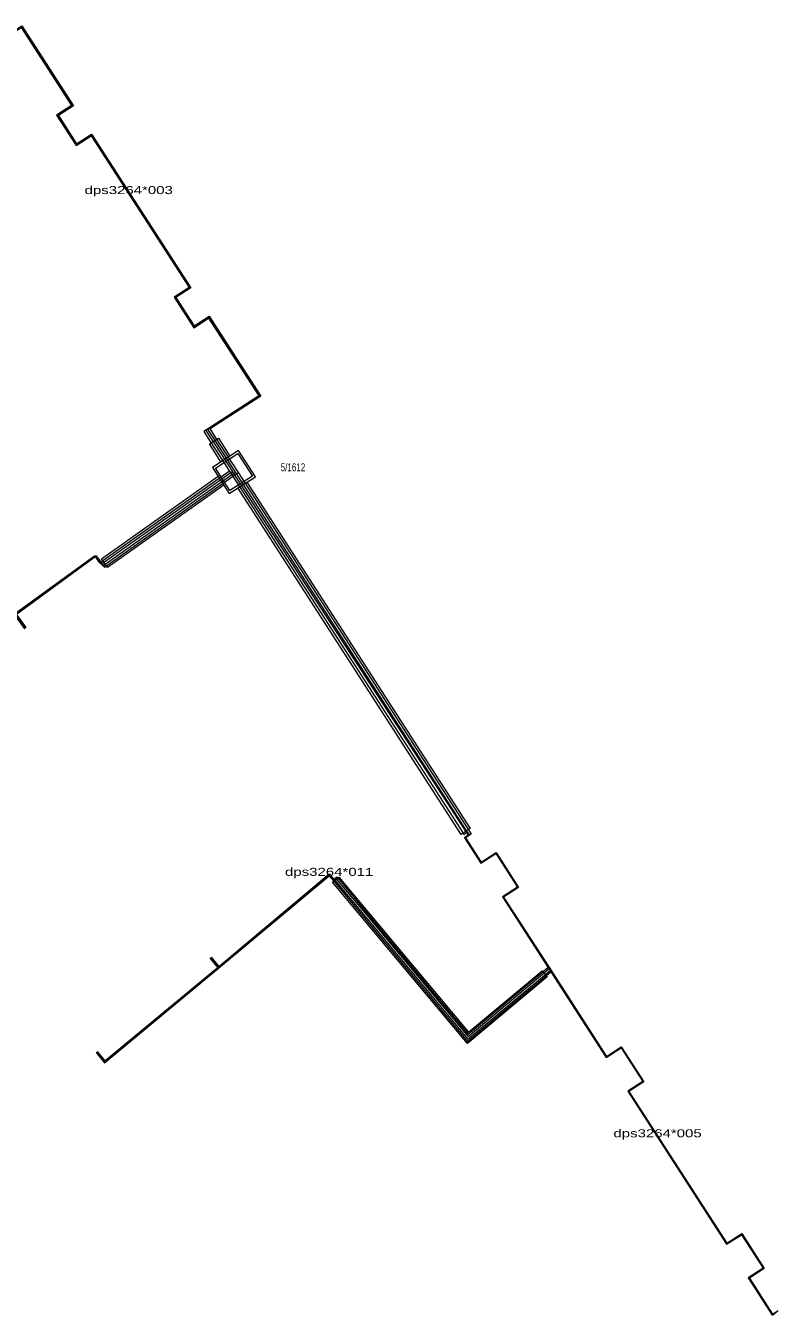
# Model space of a CAD drawing. Extents: x -473467 to -473049, y -1106745 to -1106181.
# Drawn here: x -473234.1 to -473149.4, y -1106405.6 to -1106261.1 of the extents above; entities that cross this region are included whole.
import ezdxf
from ezdxf.enums import TextEntityAlignment as Align

# ---------------------------------------------------------------- set-up
doc = ezdxf.new("R2010")
doc.units = 0
doc.header["$LTSCALE"] = 0.36
for name, color, linetype, lineweight in [('11', 7, 'Continuous', 13), ('14', 7, 'Continuous', 13), ('17', 7, 'Continuous', 13)]:
    doc.layers.add(name, color=color, linetype=linetype, lineweight=lineweight)
doc.layers.add('16', color=7, linetype='Continuous')
doc.layers.add('19', color=7, linetype='Continuous')

msp = doc.modelspace()

# ---------------------------------------------------------------- linework, layer by layer
at = {"layer": '11'}
for p, q in [((-473213.287, -1106307.887), (-473211.131, -1106311.23)), ((-473213.088, -1106307.753), (-473210.807, -1106311.29)), ((-473212.886, -1106307.623), (-473210.487, -1106311.344)), ((-473212.691, -1106307.484), (-473210.166, -1106311.398)), ((-473225.749, -1106321.547), (-473211.136, -1106311.222)), ((-473225.567, -1106321.71), (-473210.812, -1106311.283)), ((-473184.47, -1106351.851), (-473210.807, -1106311.29)), ((-473225.389, -1106321.873), (-473210.489, -1106311.341)), ((-473225.204, -1106322.031), (-473210.161, -1106311.406)), ((-473199.906, -1106356.614), (-473199.394, -1106357.227)), ((-473199.899, -1106356.544), (-473199.387, -1106357.156)), ((-473199.444, -1106357.323), (-473195.783, -1106361.702))]:
    msp.add_line(p, q, dxfattribs=at)
for points in [[(-473238.707, -1106262.643), (-473238.074, -1106263.624), (-473234.545, -1106261.347), (-473228.897, -1106270.104), (-473230.578, -1106271.188), (-473228.367, -1106274.617), (-473226.686, -1106273.533), (-473215.683, -1106290.594), (-473217.364, -1106291.678), (-473215.152, -1106295.107), (-473213.472, -1106294.023), (-473207.824, -1106302.78), (-473213.374, -1106306.359), (-473213.458, -1106306.413), (-473214.009, -1106306.769), (-473213.287, -1106307.887)], [(-473238.667, -1106262.612), (-473238.06, -1106263.555), (-473234.53, -1106261.278), (-473228.828, -1106270.119), (-473230.509, -1106271.203), (-473228.352, -1106274.548), (-473226.671, -1106273.464), (-473215.614, -1106290.609), (-473217.295, -1106291.693), (-473215.137, -1106295.038), (-473213.457, -1106293.954), (-473207.755, -1106302.795), (-473213.347, -1106306.401), (-473213.389, -1106306.428), (-473213.78, -1106306.68), (-473213.088, -1106307.753)], [(-473238.628, -1106262.581), (-473238.045, -1106263.486), (-473234.515, -1106261.209), (-473228.759, -1106270.134), (-473230.44, -1106271.218), (-473228.337, -1106274.479), (-473226.656, -1106273.395), (-473215.545, -1106290.624), (-473217.225, -1106291.708), (-473215.123, -1106294.969), (-473213.442, -1106293.885), (-473207.686, -1106302.81), (-473213.551, -1106306.592), (-473212.886, -1106307.623)], [(-473238.589, -1106262.55), (-473238.03, -1106263.416), (-473234.5, -1106261.14), (-473228.69, -1106270.149), (-473230.371, -1106271.233), (-473228.322, -1106274.41), (-473226.641, -1106273.326), (-473215.476, -1106290.639), (-473217.156, -1106291.723), (-473215.108, -1106294.9), (-473213.427, -1106293.816), (-473207.617, -1106302.825), (-473213.293, -1106306.485), (-473213.322, -1106306.504), (-473212.691, -1106307.484)], [(-473211.131, -1106311.23), (-473184.855, -1106351.973), (-473184.779, -1106352.091), (-473184.477, -1106351.896)], [(-473210.487, -1106311.344), (-473184.452, -1106351.713), (-473184.148, -1106352.184)], [(-473210.166, -1106311.398), (-473184.25, -1106351.583), (-473183.93, -1106352.079)], [(-473262.006, -1106346.747), (-473261.761, -1106346.568), (-473260.583, -1106348.184), (-473261.761, -1106346.568), (-473247.401, -1106336.104), (-473246.223, -1106337.72), (-473247.401, -1106336.104), (-473235.214, -1106327.223), (-473234.036, -1106328.84), (-473235.214, -1106327.223), (-473226.331, -1106320.75), (-473225.749, -1106321.547)], [(-473261.974, -1106346.785), (-473261.772, -1106346.637), (-473260.627, -1106348.212), (-473261.772, -1106346.637), (-473247.412, -1106336.173), (-473246.268, -1106337.757), (-473247.412, -1106336.173), (-473235.225, -1106327.293), (-473234.075, -1106328.867), (-473235.225, -1106327.293), (-473226.26, -1106320.76), (-473225.567, -1106321.71)], [(-473261.943, -1106346.824), (-473261.783, -1106346.707), (-473260.665, -1106348.257), (-473261.783, -1106346.707), (-473247.423, -1106336.243), (-473246.301, -1106337.796), (-473247.423, -1106336.243), (-473235.236, -1106327.363), (-473234.12, -1106328.911), (-473235.236, -1106327.363), (-473226.192, -1106320.772), (-473225.389, -1106321.873)], [(-473261.913, -1106346.865), (-473261.794, -1106346.777), (-473260.704, -1106348.284), (-473261.794, -1106346.777), (-473247.434, -1106336.313), (-473246.357, -1106337.834), (-473247.434, -1106336.313), (-473235.247, -1106327.433), (-473234.142, -1106328.961), (-473235.247, -1106327.433), (-473226.116, -1106320.779), (-473225.204, -1106322.031)], [(-473184.477, -1106351.896), (-473184.282, -1106352.198), (-473184.702, -1106352.469), (-473182.854, -1106355.335), (-473181.173, -1106354.251), (-473178.734, -1106358.033), (-473180.415, -1106359.117), (-473174.972, -1106367.556)], [(-473184.47, -1106351.851), (-473184.24, -1106352.207), (-473184.661, -1106352.478), (-473182.845, -1106355.294), (-473181.164, -1106354.21), (-473178.693, -1106358.042), (-473180.373, -1106359.126), (-473175.045, -1106367.388)], [(-473184.148, -1106352.184), (-473184.199, -1106352.216), (-473184.619, -1106352.487), (-473182.836, -1106355.252), (-473181.155, -1106354.168), (-473178.651, -1106358.051), (-473180.332, -1106359.135), (-473175.141, -1106367.183)], [(-473183.93, -1106352.079), (-473184.157, -1106352.225), (-473184.578, -1106352.496), (-473182.827, -1106355.211), (-473181.146, -1106354.127), (-473178.61, -1106358.06), (-473180.29, -1106359.144), (-473175.225, -1106366.998)], [(-473226.14, -1106376.613), (-473225.183, -1106377.768), (-473212.361, -1106367.157), (-473213.317, -1106366.001), (-473212.361, -1106367.157), (-473199.918, -1106356.755)], [(-473226.101, -1106376.581), (-473225.177, -1106377.698), (-473212.354, -1106367.086), (-473213.277, -1106365.973), (-473212.354, -1106367.086), (-473199.912, -1106356.685)], [(-473226.063, -1106376.549), (-473225.17, -1106377.627), (-473212.348, -1106367.015), (-473213.231, -1106365.95), (-473212.348, -1106367.015), (-473199.906, -1106356.614)], [(-473226.024, -1106376.517), (-473225.163, -1106377.557), (-473212.341, -1106366.945), (-473213.18, -1106365.92), (-473212.341, -1106366.945), (-473199.899, -1106356.544)], [(-473199.918, -1106356.755), (-473199.709, -1106357.005), (-473199.444, -1106357.323)], [(-473199.912, -1106356.685), (-473199.671, -1106356.972), (-473199.4, -1106357.297)], [(-473199.4, -1106357.297), (-473199.362, -1106357.265), (-473199.302, -1106357.215), (-473199.27, -1106357.254), (-473195.657, -1106361.575)], [(-473199.394, -1106357.227), (-473199.355, -1106357.194), (-473199.166, -1106357.036), (-473199.102, -1106357.113), (-473195.507, -1106361.414)], [(-473199.387, -1106357.156), (-473199.349, -1106357.124), (-473199.051, -1106356.875), (-473198.955, -1106356.99), (-473195.372, -1106361.276)], [(-473195.783, -1106361.702), (-473184.341, -1106375.389), (-473174.972, -1106367.557)], [(-473195.657, -1106361.575), (-473184.319, -1106375.139), (-473175.053, -1106367.393), (-473175.046, -1106367.387)], [(-473195.507, -1106361.414), (-473184.291, -1106374.83), (-473175.194, -1106367.225), (-473175.142, -1106367.182)], [(-473195.372, -1106361.276), (-473184.267, -1106374.56), (-473175.317, -1106367.078), (-473175.224, -1106367)], [(-473175.225, -1106366.998), (-473168.735, -1106377.061), (-473167.054, -1106375.977), (-473164.518, -1106379.91), (-473166.199, -1106380.994), (-473155.189, -1106398.073), (-473153.508, -1106396.989), (-473150.973, -1106400.923), (-473152.654, -1106402.006), (-473150.042, -1106406.057), (-473149.622, -1106405.786), (-473149.395, -1106405.64)], [(-473175.141, -1106367.183), (-473168.744, -1106377.102), (-473167.063, -1106376.018), (-473164.56, -1106379.901), (-473166.241, -1106380.985), (-473155.198, -1106398.114), (-473153.517, -1106397.031), (-473151.014, -1106400.914), (-473152.695, -1106401.997), (-473150.051, -1106406.099), (-473149.631, -1106405.828), (-473149.58, -1106405.795)], [(-473175.045, -1106367.388), (-473168.753, -1106377.144), (-473167.072, -1106376.06), (-473164.601, -1106379.892), (-473166.282, -1106380.976), (-473155.207, -1106398.156), (-473153.526, -1106397.072), (-473151.055, -1106400.905), (-473152.736, -1106401.988), (-473150.06, -1106406.14), (-473149.766, -1106405.951)], [(-473174.972, -1106367.556), (-473168.762, -1106377.185), (-473167.081, -1106376.101), (-473164.643, -1106379.884), (-473166.324, -1106380.967), (-473155.216, -1106398.197), (-473153.535, -1106397.114), (-473151.097, -1106400.896), (-473152.778, -1106401.979), (-473150.069, -1106406.182), (-473149.953, -1106406.107)]]:
    msp.add_lwpolyline(points, dxfattribs=at)
at = {"layer": '14'}
msp.add_lwpolyline([(-473212.707, -1106310.891), (-473210.186, -1106309.265), (-473208.56, -1106311.786), (-473211.081, -1106313.412), (-473212.707, -1106310.891)], close=True, dxfattribs=at)
at = {"layer": '17'}
for points in [[(-473212.086, -1106310.193), (-473213.38, -1106308.185), (-473212.372, -1106307.535), (-473211.078, -1106309.543)], [(-473208.214, -1106311.861), (-473210.111, -1106308.919), (-473213.053, -1106310.816), (-473211.156, -1106313.758)], [(-473212.403, -1106311.823), (-473211.752, -1106312.832), (-473224.847, -1106322.086), (-473225.54, -1106321.105)], [(-473210.189, -1106313.134), (-473209.176, -1106312.481), (-473184.054, -1106351.444), (-473185.065, -1106352.091)], [(-473175.389, -1106368.115), (-473184.361, -1106375.616), (-473199.53, -1106357.471), (-473198.839, -1106356.893), (-473198.839, -1106356.893), (-473184.248, -1106374.348), (-473175.966, -1106367.424)]]:
    msp.add_lwpolyline(points, close=True, dxfattribs=at)

# ---------------------------------------------------------------- texts
at = {"layer": '16', "width": 0.75}
msp.add_text('5/1612', height=0.9, dxfattribs=at).set_placement((-473205.367, -1106311.255))
at = {"layer": '19', "width": 1.4}
for s, p in [('dps3264*003', (-473222.465, -1106280.078)), ('dps3264*011', (-473199.918, -1106356.755)), ('dps3264*005', (-473162.975, -1106386.161))]:
    msp.add_text(s, height=0.9, dxfattribs=at).set_placement(p, align=Align.CENTER)

doc.saveas('drawing.dxf')
